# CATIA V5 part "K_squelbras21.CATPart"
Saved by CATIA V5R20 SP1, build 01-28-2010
Part number: squelbras21
Publications: "longueurbras21", "longueurdroitespivot"
Bounding box of the stored display mesh (mm): x -87 to 0, y -1.5 to 1.5, z -15 to 15
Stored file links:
  G:\Khaled_CFAO_2011\SIL\SIL_GR2\zthiebault\Khaled\CAD_ThinkMOTION\K_squelbras21.CATPart
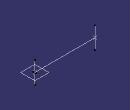
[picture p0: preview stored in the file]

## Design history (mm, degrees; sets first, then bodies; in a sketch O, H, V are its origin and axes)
Parameters
  longueurbras21 = 87 mm
  longueurdroitespivot = 30 mm
Line1: type Normal, RefPoint Point1, RefSkin yz-plane, Start -87 {= -longueurbras21}, End 0
Set1 "setgéombras21"
  Point1: (0, 0, 0)
  Line2: type Normal, RefPoint Point1, RefSkin xy-plane, Start -15 {= -longueurdroitespivot /2}, End 15 {= longueurdroitespivot /2}
  Line3: type Normal, RefPoint vertex of Line1, RefSkin xy-plane, Start -15 {= -longueurdroitespivot /2}, End 15 {= longueurdroitespivot /2}
  Plane1: type OffsetPt, RefPlane xy-plane, RefPoint vertex of Line1
  Point2: (0, 0, 0), relative to vertex of Line1
  Line4: type Normal, RefPoint Point1, RefSkin zx-plane, Start -1.5, End 1.5
Body1 (main body)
